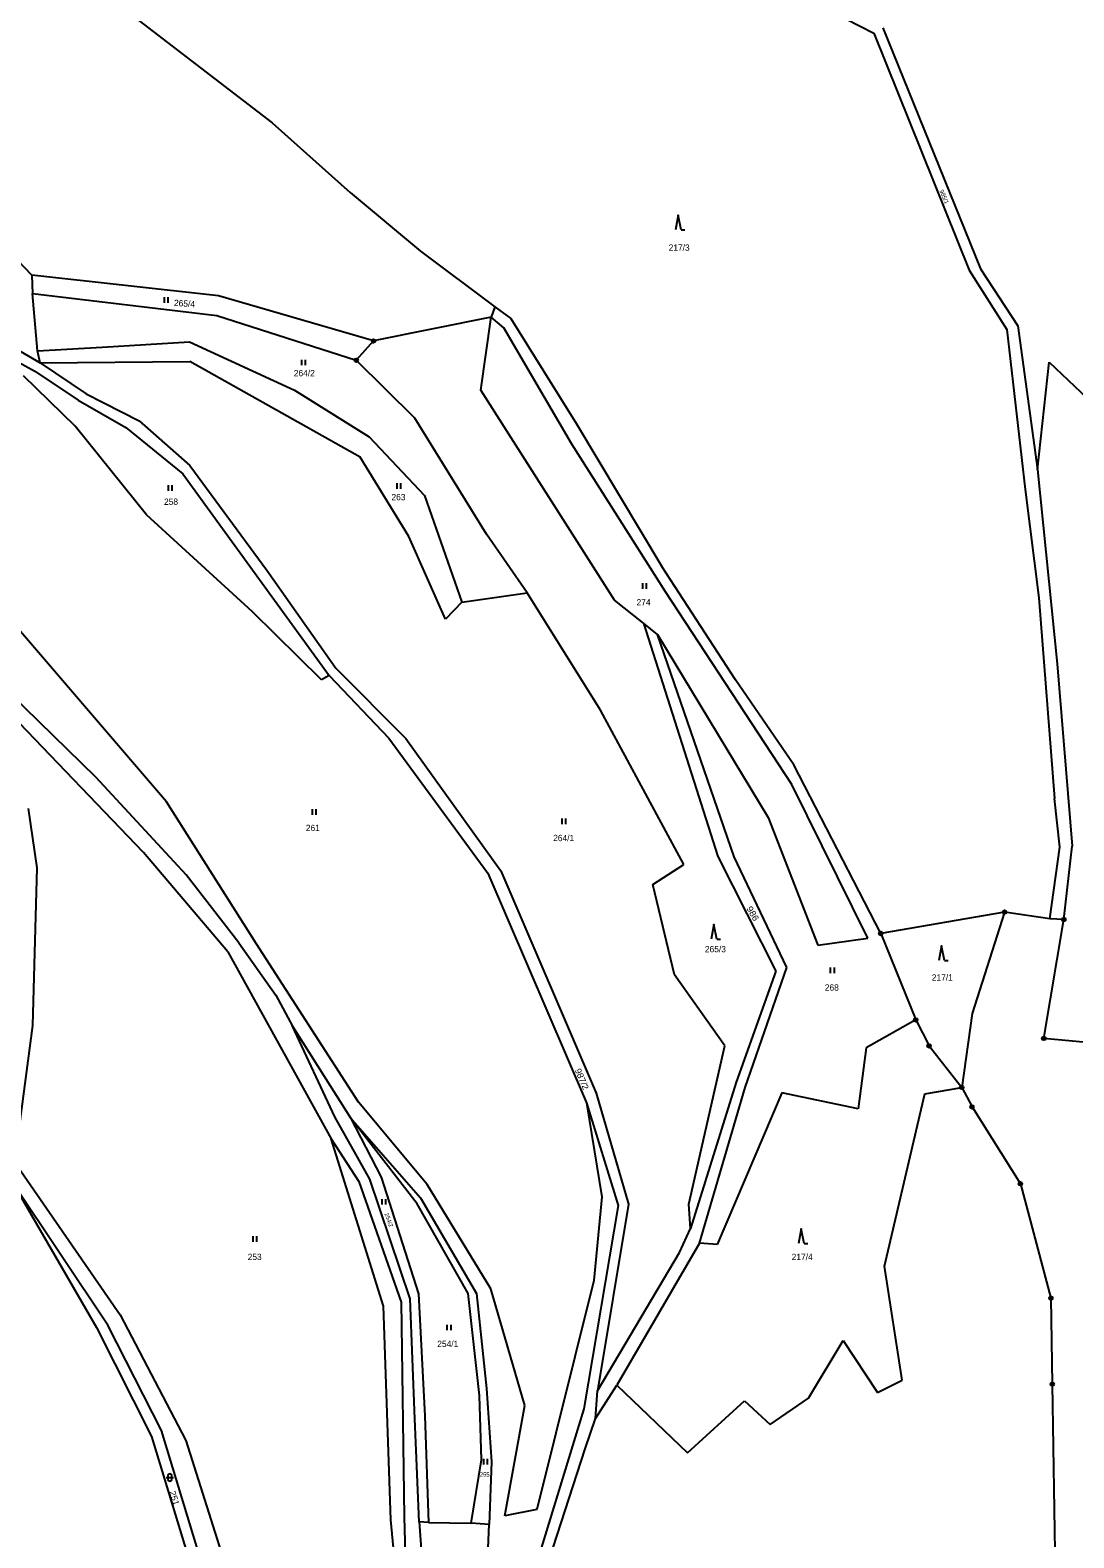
# Model space of a CAD drawing. Extents: x -754970 to -752637, y -970569 to -968179.
# Drawn here: x -753255.8 to -752973.4, y -969116.9 to -968708.9 of the extents above; entities that cross this region are included whole.
import ezdxf
from ezdxf.enums import TextEntityAlignment as Align

# ---------------------------------------------------------------- set-up
doc = ezdxf.new("R2010")
doc.units = 0
doc.header["$LTSCALE"] = 0.68
for name, color, linetype, lineweight in [('1', 7, 'Continuous', 25), ('3', 7, 'Continuous', 25), ('8', 7, 'Continuous', 25)]:
    doc.layers.add(name, color=color, linetype=linetype, lineweight=lineweight)
doc.layers.add('2', color=7, linetype='Continuous')

msp = doc.modelspace()

# ---------------------------------------------------------------- linework, layer by layer
at = {"layer": '1'}
for p, q in [((-753056.64, -968694.65), (-753027.52, -968709.73)), ((-753230.32, -968703.37), (-753190.33, -968733.98)), ((-753027.52, -968709.73), (-753001.7, -968773.89)), ((-753025.09, -968708.28), (-752998.67, -968773.52)), ((-753190.33, -968733.98), (-753169.24, -968752.9)), ((-753255.44, -968775.22), (-753278.36, -968751.33)), ((-753169.24, -968752.9), (-753150.2, -968768.78)), ((-753150.2, -968768.78), (-753130.09, -968783.82)), ((-753204.88, -968780.8), (-753255.44, -968775.22)), ((-753255.44, -968775.22), (-753255.2, -968780.19)), ((-753001.7, -968773.89), (-752991.52, -968789.9)), ((-752998.67, -968773.52), (-752988.6, -968788.93)), ((-753255.2, -968780.19), (-753205.37, -968786.13)), ((-753253.86, -968795.71), (-753255.2, -968780.19)), ((-753281.51, -968782.37), (-753253.14, -968798.99)), ((-753162.89, -968793.04), (-753204.88, -968780.8)), ((-753130.09, -968783.82), (-753131.06, -968786.61)), ((-753130.09, -968783.82), (-753125.73, -968786.97)), ((-753282.11, -968786.25), (-753254.59, -968801.17)), ((-753205.37, -968786.13), (-753167.62, -968798.27)), ((-753127.67, -968789.52), (-753131.06, -968786.61)), ((-753125.73, -968786.97), (-753108.03, -968815.47)), ((-753109.24, -968820.93), (-753127.67, -968789.52)), ((-752991.52, -968789.9), (-752986.55, -968833.2)), ((-752988.6, -968788.93), (-752983.27, -968827.86)), ((-753253.86, -968795.71), (-753236.36, -968794.72)), ((-753253.14, -968798.99), (-753253.86, -968795.71)), ((-753236.36, -968794.72), (-753212.77, -968793.28)), ((-753212.77, -968793.28), (-753184.27, -968806.38)), ((-753162.89, -968793.04), (-753167.62, -968798.27)), ((-753253.14, -968798.99), (-753212.65, -968798.62)), ((-753253.14, -968798.99), (-753240.65, -968807.36)), ((-753166.57, -968824.45), (-753212.65, -968798.62)), ((-753151.78, -968813.89), (-753167.62, -968798.27)), ((-752983.27, -968827.86), (-752980.13, -968798.76)), ((-752980.13, -968798.76), (-752968.12, -968810.16)), ((-753243.68, -968816.09), (-753257.62, -968802.51)), ((-753254.59, -968801.17), (-753242.83, -968809.05)), ((-753240.65, -968807.36), (-753226.34, -968814.63)), ((-753184.27, -968806.38), (-753164.14, -968818.99)), ((-753097.72, -968863.14), (-753133.86, -968806.38)), ((-753242.83, -968809.05), (-753229.98, -968816.45)), ((-753224.39, -968840.11), (-753243.68, -968816.09)), ((-753229.98, -968816.45), (-753214.57, -968828.96)), ((-753226.34, -968814.63), (-753212.63, -968826.77)), ((-753132.38, -968845.31), (-753151.78, -968813.89)), ((-753108.03, -968815.47), (-753084.87, -968854.04)), ((-753164.14, -968818.99), (-753149.11, -968834.88)), ((-753083.9, -968860.95), (-753109.24, -968820.93)), ((-753153.35, -968845.92), (-753166.57, -968824.45)), ((-753214.57, -968828.96), (-753174.93, -968883.53)), ((-753212.63, -968826.77), (-753191.78, -968855.03)), ((-752983.27, -968827.86), (-752977.95, -968880.38)), ((-752986.55, -968833.2), (-752982.92, -968862.55)), ((-753149.11, -968834.88), (-753139.05, -968863.74)), ((-753195.66, -968866.31), (-753224.39, -968840.11)), ((-753121.37, -968861.2), (-753132.38, -968845.31)), ((-753143.41, -968868.35), (-753153.35, -968845.92)), ((-753191.78, -968855.03), (-753173.11, -968881.59)), ((-753064.99, -968884.72), (-753084.87, -968854.04)), ((-753139.05, -968863.74), (-753121.37, -968861.2)), ((-753101.48, -968892.97), (-753121.37, -968861.2)), ((-753049.71, -968913.1), (-753083.9, -968860.95)), ((-753139.05, -968863.74), (-753143.41, -968868.35)), ((-753089.84, -968869.44), (-753097.72, -968863.14)), ((-752982.92, -968862.55), (-752978.68, -968916.88)), ((-753176.99, -968884.74), (-753195.66, -968866.31)), ((-753086.08, -968872.48), (-753089.84, -968869.44)), ((-753089.84, -968869.44), (-753069.71, -968932.51)), ((-753065.35, -968932.63), (-753086.08, -968872.48)), ((-753086.08, -968872.48), (-753056.13, -968921.96)), ((-753173.11, -968881.59), (-753154.2, -968900.63)), ((-752977.95, -968880.38), (-752973.83, -968929.73)), ((-753225.14, -968931.48), (-753269.98, -968884.76)), ((-753266.58, -968883.32), (-753238.13, -968910.95)), ((-753174.93, -968883.53), (-753176.99, -968884.74)), ((-753174.93, -968883.53), (-753158.8, -968900.51)), ((-753049.22, -968907.77), (-753064.99, -968884.72)), ((-753078.93, -968934.69), (-753101.48, -968892.97)), ((-753158.8, -968900.51), (-753132.01, -968937.01)), ((-753154.2, -968900.63), (-753128.49, -968936.4)), ((-753238.13, -968910.95), (-753213.6, -968937.46)), ((-753025.67, -968953.38), (-753049.22, -968907.77)), ((-753029.12, -968954.6), (-753049.71, -968913.1)), ((-753194.73, -968956.11), (-753218.96, -968917.76)), ((-752977.22, -968929.98), (-752978.68, -968916.88)), ((-753256.38, -968919.51), (-753254.01, -968935.6)), ((-753056.13, -968921.96), (-753042.7, -968956.54)), ((-752979.89, -968949.38), (-752977.22, -968929.98)), ((-752976.12, -968949.62), (-752973.83, -968929.73)), ((-753202.36, -968958.38), (-753225.14, -968931.48)), ((-753087.3, -968940.15), (-753078.93, -968934.69)), ((-753069.71, -968932.51), (-753054.08, -968963.56)), ((-753051.05, -968962.59), (-753065.35, -968932.63)), ((-753254.01, -968935.6), (-753255.25, -968978.28)), ((-753199.37, -968955.91), (-753213.6, -968937.46)), ((-753132.01, -968937.01), (-753105.25, -968999.21)), ((-753128.49, -968936.4), (-753102.7, -968996.55)), ((-753081.48, -968964.53), (-753087.3, -968940.15)), ((-752992.16, -968947.58), (-753025.67, -968953.38)), ((-752992.16, -968947.58), (-753000.94, -968975.04)), ((-752979.89, -968949.38), (-752992.16, -968947.58)), ((-752981.53, -968981.79), (-752976.12, -968949.62)), ((-752976.12, -968949.62), (-752979.89, -968949.38)), ((-753042.7, -968956.54), (-753029.12, -968954.6)), ((-753025.67, -968953.38), (-753016.19, -968976.78)), ((-753202.36, -968958.38), (-753174.42, -969008.9)), ((-753199.37, -968955.91), (-753189.37, -968970.03)), ((-753167, -968999), (-753194.73, -968956.11)), ((-753054.08, -968963.56), (-753064.75, -968993.63)), ((-753062.32, -968995.09), (-753051.05, -968962.59)), ((-753067.9, -968983.81), (-753081.48, -968964.53)), ((-753189.37, -968970.03), (-753184.84, -968978.49)), ((-753000.94, -968975.04), (-753003.74, -968995.05)), ((-753255.25, -968978.28), (-753260.1, -969015.15)), ((-753173.39, -969003.02), (-753184.84, -968978.49)), ((-753184.84, -968978.49), (-753169.17, -969003.23)), ((-753016.19, -968976.78), (-753029.59, -968984.3)), ((-753016.19, -968976.78), (-753012.58, -968983.79)), ((-753077.61, -969026.62), (-753067.9, -968983.81)), ((-753029.59, -968984.3), (-753031.77, -969000.79)), ((-753012.58, -968983.79), (-753003.74, -968995.05)), ((-752951.05, -968984.64), (-752981.53, -968981.79)), ((-753102.7, -968996.55), (-753093.97, -969026.62)), ((-753064.75, -968993.63), (-753077.12, -969033.17)), ((-753074.7, -969037.17), (-753062.32, -968995.09)), ((-753052.39, -968996.54), (-753069.97, -969037.54)), ((-753031.77, -969000.79), (-753052.39, -968996.54)), ((-753013.7, -968996.79), (-753003.74, -968995.05)), ((-753003.74, -968995.05), (-753000.97, -969000.32)), ((-753148.45, -969021.27), (-753167, -968999)), ((-753105.25, -968999.21), (-753096.76, -969026.99)), ((-753105.25, -968999.21), (-753101.13, -969024.68)), ((-753024.62, -969043.36), (-753013.7, -968996.79)), ((-753000.97, -969000.32), (-752987.88, -969021.09)), ((-753163.91, -969019.83), (-753173.39, -969003.02)), ((-753169.17, -969003.23), (-753160.87, -969019.36)), ((-753151.13, -969026.53), (-753169.17, -969003.23)), ((-753169.17, -969003.23), (-753150.2, -969024.88)), ((-753160.25, -969054.26), (-753174.42, -969008.9)), ((-753174.42, -969008.9), (-753166.9, -969020.45)), ((-753260.1, -969015.15), (-753231.5, -969056.59)), ((-753260.42, -969021), (-753237.86, -969059.98)), ((-753234.81, -969059.33), (-753260.42, -969021)), ((-753166.9, -969020.45), (-753155.46, -969053.14)), ((-753152.99, -969052.21), (-753163.91, -969019.83)), ((-753160.87, -969019.36), (-753150.72, -969050.87)), ((-752987.88, -969021.09), (-752979.63, -969052.03)), ((-753150.2, -969024.88), (-753135.05, -969050.77)), ((-753131.14, -969049.53), (-753148.45, -969021.27)), ((-753101.13, -969024.68), (-753103.31, -969047.24)), ((-753137.32, -969050.77), (-753151.13, -969026.53)), ((-753096.76, -969026.99), (-753105.99, -969082.01)), ((-753093.97, -969026.62), (-753102.28, -969077.16)), ((-753077.12, -969033.17), (-753077.61, -969026.62)), ((-753080.15, -969039.72), (-753077.12, -969033.17)), ((-753074.7, -969037.17), (-753097.12, -969075.62)), ((-753069.97, -969037.54), (-753074.7, -969037.17)), ((-753102.28, -969077.16), (-753080.15, -969039.72)), ((-753019.91, -969074.28), (-753024.62, -969043.36)), ((-753121.96, -969081.08), (-753131.14, -969049.53)), ((-753103.31, -969047.24), (-753118.75, -969109.27)), ((-753155.46, -969053.14), (-753154.63, -969111.19)), ((-753151.75, -969084.69), (-753152.99, -969052.21)), ((-753150.72, -969050.87), (-753149.07, -969083.86)), ((-753134.23, -969078.4), (-753137.32, -969050.77)), ((-753135.05, -969050.77), (-753132.37, -969076.54)), ((-752979.63, -969052.03), (-752979.25, -969075.31)), ((-753231.5, -969056.59), (-753213.71, -969090.59)), ((-753158.28, -969112.06), (-753160.25, -969054.26)), ((-753237.86, -969059.98), (-753223.05, -969089.46)), ((-753220.31, -969087.85), (-753234.81, -969059.33)), ((-753045.25, -969079.11), (-753035.88, -969063.51)), ((-753035.88, -969063.51), (-753026.59, -969077.63)), ((-753132.37, -969076.54), (-753131.03, -969096.34)), ((-753102.89, -969084.59), (-753097.12, -969075.62)), ((-753102.89, -969084.59), (-753102.28, -969077.16)), ((-753097.12, -969075.62), (-753077.93, -969093.88)), ((-753026.59, -969077.63), (-753019.91, -969074.28)), ((-752979.25, -969075.31), (-752978.27, -969137.19)), ((-753133.71, -969095.82), (-753134.23, -969078.4)), ((-753127.42, -969110.98), (-753121.96, -969081.08)), ((-753105.99, -969082.01), (-753119.76, -969126.8)), ((-753077.93, -969093.88), (-753062.52, -969079.85)), ((-753062.52, -969079.85), (-753055.55, -969086.26)), ((-753055.55, -969086.26), (-753045.25, -969079.11)), ((-753150.61, -969112.63), (-753151.75, -969084.69)), ((-753149.07, -969083.86), (-753148.03, -969112.73)), ((-753105.68, -969092.84), (-753102.89, -969084.59)), ((-753223.05, -969089.46), (-753206.01, -969145.03)), ((-753193.33, -969176.6), (-753220.31, -969087.85)), ((-753213.71, -969090.59), (-753192.12, -969158.88)), ((-753117.5, -969129.3), (-753105.68, -969092.84)), ((-753136.49, -969112.94), (-753133.71, -969095.82)), ((-753131.03, -969096.34), (-753131.64, -969113.35)), ((-753118.75, -969109.27), (-753127.42, -969110.98)), ((-753154.74, -969147.17), (-753158.28, -969112.06)), ((-753154.63, -969111.19), (-753154.37, -969121.24)), ((-753150.61, -969112.63), (-753148.66, -969138.92)), ((-753148.03, -969112.73), (-753150.61, -969112.63)), ((-753148.03, -969112.73), (-753136.49, -969112.94)), ((-753131.64, -969113.35), (-753136.49, -969112.94)), ((-753132.25, -969128.26), (-753131.64, -969113.35))]:
    msp.add_line(p, q, dxfattribs=at)
for points in [[(-753133.86, -968806.38), (-753131.06, -968786.61), (-753162.89, -968793.04)], [(-753218.96, -968917.76), (-753259.57, -968870.43), (-753336.25, -968814.29)]]:
    msp.add_lwpolyline(points, dxfattribs=at)
at = {"layer": '3'}
for p, q in [((-753079.71, -968762.98), (-753078.714, -968762.98)), ((-753219.511, -968782.69), (-753219.511, -968781.19)), ((-753218.51, -968782.69), (-753218.51, -968781.19)), ((-753182.321, -968799.61), (-753182.321, -968798.11)), ((-753181.32, -968799.61), (-753181.32, -968798.11)), ((-753218.401, -968833.6), (-753218.401, -968832.1)), ((-753217.4, -968833.6), (-753217.4, -968832.1)), ((-753156.531, -968833.04), (-753156.531, -968831.54)), ((-753155.53, -968833.04), (-753155.53, -968831.54)), ((-753090.081, -968860.1), (-753090.081, -968858.6)), ((-753089.08, -968860.1), (-753089.08, -968858.6)), ((-753179.441, -968921.25), (-753179.441, -968919.75)), ((-753178.44, -968921.25), (-753178.44, -968919.75)), ((-753111.881, -968923.79), (-753111.881, -968922.29)), ((-753110.88, -968923.79), (-753110.88, -968922.29)), ((-753070.05, -968954.94), (-753069.054, -968954.94)), ((-753039.221, -968964.08), (-753039.221, -968962.58)), ((-753038.22, -968964.08), (-753038.22, -968962.58)), ((-753008.45, -968960.71), (-753007.454, -968960.71)), ((-753160.561, -969026.73), (-753160.561, -969025.23)), ((-753159.56, -969026.73), (-753159.56, -969025.23)), ((-753195.511, -969036.79), (-753195.511, -969035.29)), ((-753194.51, -969036.79), (-753194.51, -969035.29)), ((-753046.41, -969037.31), (-753045.414, -969037.31)), ((-753142.961, -969060.75), (-753142.961, -969059.25)), ((-753141.96, -969060.75), (-753141.96, -969059.25)), ((-753133.051, -969097.03), (-753133.051, -969095.53)), ((-753132.05, -969097.03), (-753132.05, -969095.53)), ((-753219.051, -969100.591), (-753217.049, -969100.591)), ((-753218.551, -969100.091), (-753218.551, -969101.092)), ((-753217.549, -969101.092), (-753217.549, -969100.091))]:
    msp.add_line(p, q, dxfattribs=at)
for points in [[(-753079.71, -968762.98), (-753080.46, -968758.98), (-753081.21, -968762.98)], [(-753070.05, -968954.94), (-753070.8, -968950.94), (-753071.55, -968954.94)], [(-753008.45, -968960.71), (-753009.2, -968956.71), (-753009.95, -968960.71)], [(-753046.41, -969037.31), (-753047.16, -969033.31), (-753047.91, -969037.31)]]:
    msp.add_lwpolyline(points, dxfattribs=at)
for centre, start, end in [((-753218.05, -969100.0909), 0, 180), ((-753218.05, -969101.0909), 180, 359.98789)]:
    msp.add_arc(centre, 0.5, start, end, dxfattribs=at)
at = {"layer": '8'}
for centre, radius in [((-753162.89, -968793.0399), 0.5), ((-753162.89, -968793.0399), 0.0303), ((-753167.62, -968798.2699), 0.5), ((-753167.62, -968798.2699), 0.0303), ((-752992.16, -968947.5799), 0.5), ((-752992.16, -968947.5799), 0.0303), ((-752976.12, -968949.6199), 0.5), ((-752976.12, -968949.6199), 0.0303), ((-753025.67, -968953.3799), 0.5), ((-753025.67, -968953.3799), 0.0303), ((-753016.19, -968976.7799), 0.5), ((-753016.19, -968976.7799), 0.0303), ((-753012.58, -968983.7899), 0.5), ((-753012.58, -968983.7899), 0.0303), ((-752981.53, -968981.7899), 0.5), ((-752981.53, -968981.7899), 0.0303), ((-753003.74, -968995.0499), 0.5), ((-753003.74, -968995.0499), 0.0303), ((-753000.97, -969000.3199), 0.5), ((-753000.97, -969000.3199), 0.0303), ((-752987.88, -969021.0899), 0.5), ((-752987.88, -969021.0899), 0.0303), ((-752979.63, -969052.0299), 0.5), ((-752979.63, -969052.0299), 0.0303), ((-752979.25, -969075.3099), 0.5), ((-752979.25, -969075.3099), 0.0303)]:
    msp.add_circle(centre, radius, dxfattribs=at)

# ---------------------------------------------------------------- texts
at = {"layer": '2'}
for s, height, rotation, width, p in [('985/1', 1.14, 293, 1.05, (-753009.0137, -968754.2343)), ('986', 1.7, 300, 1.1, (-753061.0326, -968948.408)), ('987/2', 1.7, 293, 1.05, (-753107.319, -968993.0949)), ('251', 1.7, 287, 1.05, (-753217.6274, -969106.38))]:
    msp.add_text(s, height=height, rotation=rotation, dxfattribs=dict(at, width=width)).set_placement(p, align=Align.CENTER)
for s, height, p in [('217/3', 1.7, (-753080.22, -968768.625)), ('264/2', 1.7, (-753181.66, -968802.585)), ('258', 1.7, (-753217.729, -968837.385)), ('263', 1.7, (-753156.179, -968836.135)), ('274', 1.7, (-753089.849, -968864.595)), ('261', 1.7, (-753179.359, -968925.665)), ('264/1', 1.7, (-753111.47, -968928.385)), ('265/3', 1.7, (-753070.41, -968958.455)), ('268', 1.7, (-753038.909, -968968.845)), ('217/1', 1.7, (-753009, -968966.135)), ('253', 1.7, (-753195.089, -969041.745)), ('217/4', 1.7, (-753046.93, -969041.755)), ('254/1', 1.7, (-753142.84, -969065.285)), ('255', 1.14, (-753132.84, -969100.355))]:
    msp.add_text(s, height=height, dxfattribs=at).set_placement(p, align=Align.CENTER)
for s, height, rotation, p in [('265/4', 1.7, 356, (-753214.1383, -968783.736)), ('254/2', 1.14, 290, (-753159.3214, -969031.0865))]:
    msp.add_text(s, height=height, rotation=rotation, dxfattribs=at).set_placement(p, align=Align.CENTER)

doc.saveas('drawing.dxf')
